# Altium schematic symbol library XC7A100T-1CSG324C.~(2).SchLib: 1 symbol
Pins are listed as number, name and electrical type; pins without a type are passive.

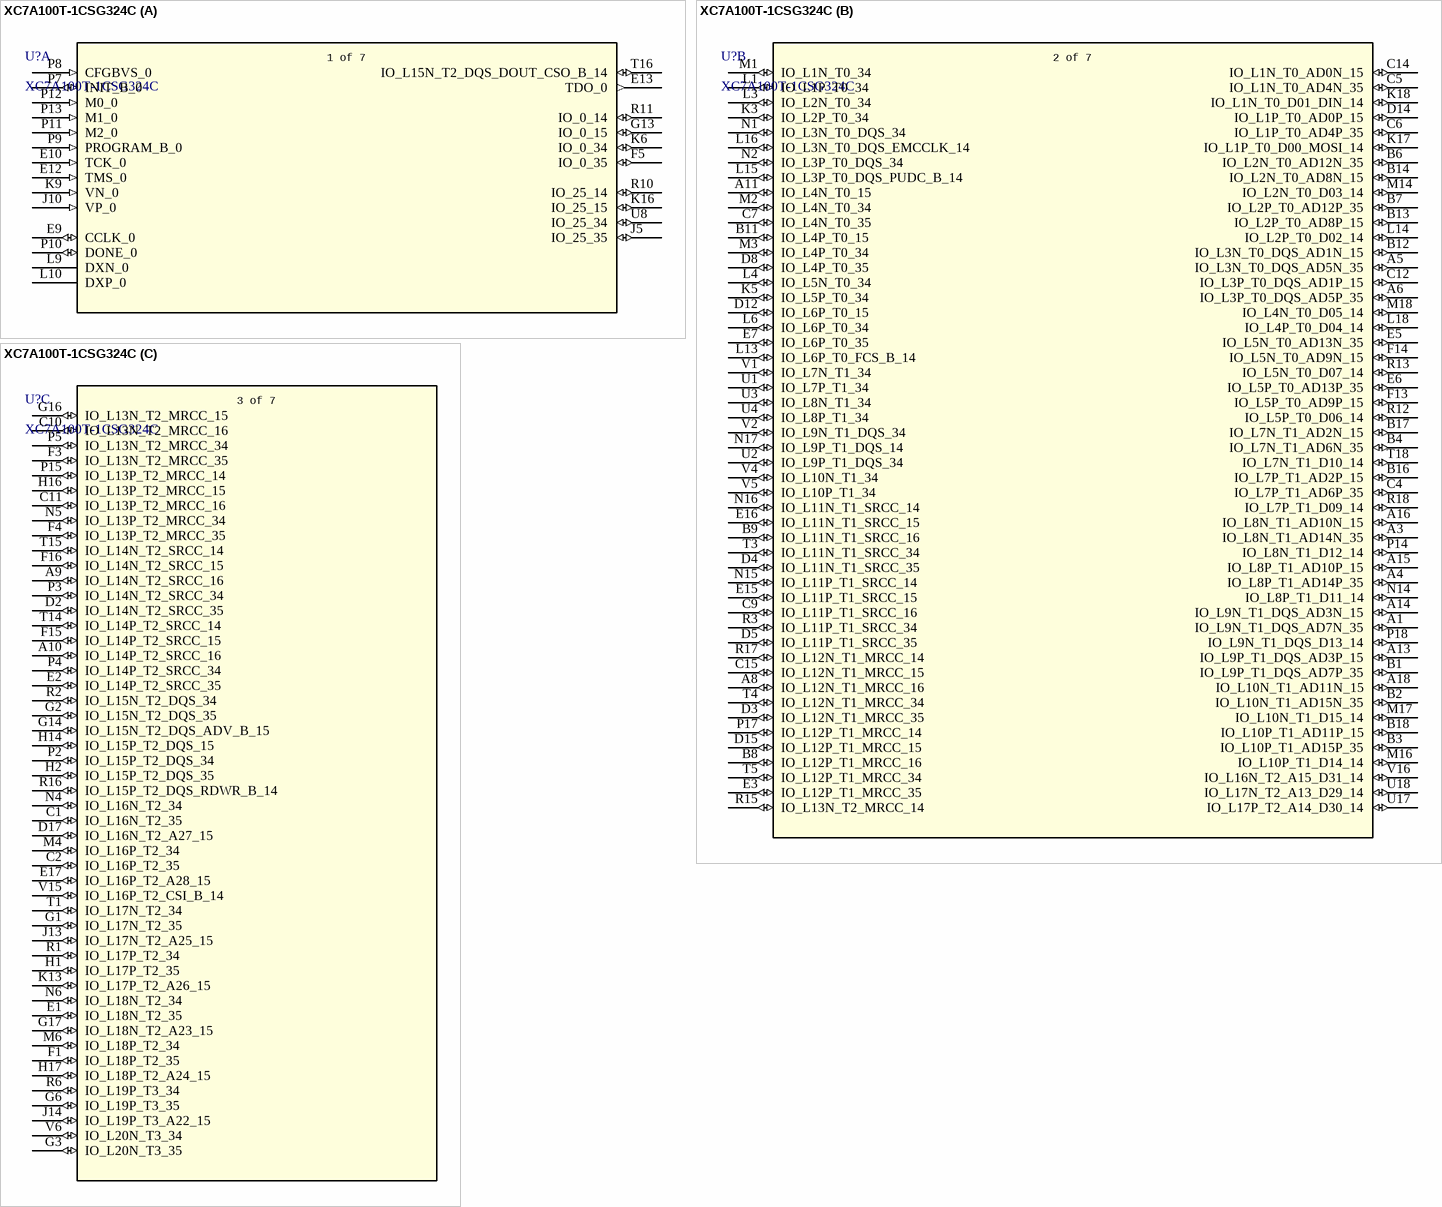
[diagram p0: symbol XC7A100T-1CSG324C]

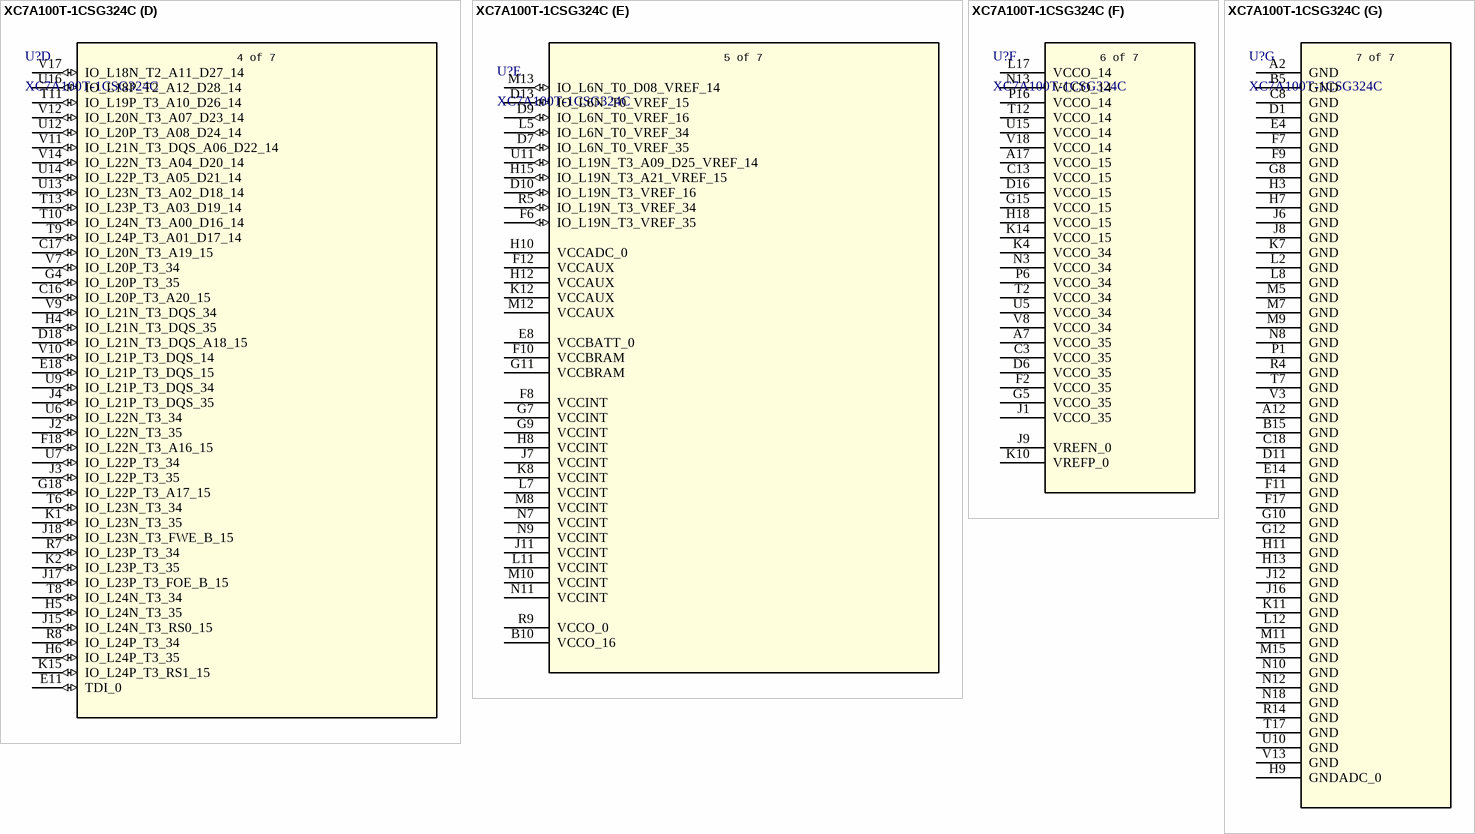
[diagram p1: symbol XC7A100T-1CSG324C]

## XC7A100T-1CSG324C
designator U?
Description; Manufacturer_Name: Xilinx Inc
footprint CSG324_XIL
part A pins: E9 CCLK_0 (io), E10 TCK_0 (in), E12 TMS_0 (in), E13 TDO_0 (out), F5 IO_0_35 (io), G13 IO_0_15 (io), J5 IO_25_35 (io), J10 VP_0 (in), K6 IO_0_34 (io), K9 VN_0 (in), K16 IO_25_15 (io), L9 DXN_0, L10 DXP_0, P7 INIT_B_0 (io), P8 CFGBVS_0 (in), P9 PROGRAM_B_0 (in), P10 DONE_0 (io), P11 M2_0 (in), P12 M0_0 (in), P13 M1_0 (in), R10 IO_25_14 (io), R11 IO_0_14 (io), T16 IO_L15N_T2_DQS_DOUT_CSO_B_14 (io), U8 IO_25_34 (io)
part B pins: A1 IO_L9N_T1_DQS_AD7N_35 (io), A3 IO_L8N_T1_AD14N_35 (io), A4 IO_L8P_T1_AD14P_35 (io), A5 IO_L3N_T0_DQS_AD5N_35 (io), A6 IO_L3P_T0_DQS_AD5P_35 (io), A8 IO_L12N_T1_MRCC_16 (io), A11 IO_L4N_T0_15 (io), A13 IO_L9P_T1_DQS_AD3P_15 (io), A14 IO_L9N_T1_DQS_AD3N_15 (io), A15 IO_L8P_T1_AD10P_15 (io), A16 IO_L8N_T1_AD10N_15 (io), A18 IO_L10N_T1_AD11N_15 (io), B1 IO_L9P_T1_DQS_AD7P_35 (io), B2 IO_L10N_T1_AD15N_35 (io), B3 IO_L10P_T1_AD15P_35 (io), B4 IO_L7N_T1_AD6N_35 (io), B6 IO_L2N_T0_AD12N_35 (io), B7 IO_L2P_T0_AD12P_35 (io), B8 IO_L12P_T1_MRCC_16 (io), B9 IO_L11N_T1_SRCC_16 (io), B11 IO_L4P_T0_15 (io), B12 IO_L3N_T0_DQS_AD1N_15 (io), B13 IO_L2P_T0_AD8P_15 (io), B14 IO_L2N_T0_AD8N_15 (io), B16 IO_L7P_T1_AD2P_15 (io), B17 IO_L7N_T1_AD2N_15 (io), B18 IO_L10P_T1_AD11P_15 (io), C4 IO_L7P_T1_AD6P_35 (io), C5 IO_L1N_T0_AD4N_35 (io), C6 IO_L1P_T0_AD4P_35 (io), C7 IO_L4N_T0_35 (io), C9 IO_L11P_T1_SRCC_16 (io), C12 IO_L3P_T0_DQS_AD1P_15 (io), C14 IO_L1N_T0_AD0N_15 (io), C15 IO_L12N_T1_MRCC_15 (io), D3 IO_L12N_T1_MRCC_35 (io), D4 IO_L11N_T1_SRCC_35 (io), D5 IO_L11P_T1_SRCC_35 (io), D8 IO_L4P_T0_35 (io), D12 IO_L6P_T0_15 (io), D14 IO_L1P_T0_AD0P_15 (io), D15 IO_L12P_T1_MRCC_15 (io), E3 IO_L12P_T1_MRCC_35 (io), E5 IO_L5N_T0_AD13N_35 (io), E6 IO_L5P_T0_AD13P_35 (io), E7 IO_L6P_T0_35 (io), E15 IO_L11P_T1_SRCC_15 (io), E16 IO_L11N_T1_SRCC_15 (io), F13 IO_L5P_T0_AD9P_15 (io), F14 IO_L5N_T0_AD9N_15 (io), K3 IO_L2P_T0_34 (io), K5 IO_L5P_T0_34 (io), K17 IO_L1P_T0_D00_MOSI_14 (io), K18 IO_L1N_T0_D01_DIN_14 (io), L1 IO_L1P_T0_34 (io), L3 IO_L2N_T0_34 (io), L4 IO_L5N_T0_34 (io), L6 IO_L6P_T0_34 (io), L13 IO_L6P_T0_FCS_B_14 (io), L14 IO_L2P_T0_D02_14 (io), L15 IO_L3P_T0_DQS_PUDC_B_14 (io), L16 IO_L3N_T0_DQS_EMCCLK_14 (io), L18 IO_L4P_T0_D04_14 (io), M1 IO_L1N_T0_34 (io), M2 IO_L4N_T0_34 (io), M3 IO_L4P_T0_34 (io), M14 IO_L2N_T0_D03_14 (io), M16 IO_L10P_T1_D14_14 (io), M17 IO_L10N_T1_D15_14 (io), M18 IO_L4N_T0_D05_14 (io), N1 IO_L3N_T0_DQS_34 (io), N2 IO_L3P_T0_DQS_34 (io), N14 IO_L8P_T1_D11_14 (io), N15 IO_L11P_T1_SRCC_14 (io), N16 IO_L11N_T1_SRCC_14 (io), N17 IO_L9P_T1_DQS_14 (io), P14 IO_L8N_T1_D12_14 (io), P17 IO_L12P_T1_MRCC_14 (io), P18 IO_L9N_T1_DQS_D13_14 (io), R3 IO_L11P_T1_SRCC_34 (io), R12 IO_L5P_T0_D06_14 (io), R13 IO_L5N_T0_D07_14 (io), R15 IO_L13N_T2_MRCC_14 (io), R17 IO_L12N_T1_MRCC_14 (io), R18 IO_L7P_T1_D09_14 (io), T3 IO_L11N_T1_SRCC_34 (io), T4 IO_L12N_T1_MRCC_34 (io), T5 IO_L12P_T1_MRCC_34 (io), T18 IO_L7N_T1_D10_14 (io), U1 IO_L7P_T1_34 (io), U2 IO_L9P_T1_DQS_34 (io), U3 IO_L8N_T1_34 (io), U4 IO_L8P_T1_34 (io), U17 IO_L17P_T2_A14_D30_14 (io), U18 IO_L17N_T2_A13_D29_14 (io), V1 IO_L7N_T1_34 (io), V2 IO_L9N_T1_DQS_34 (io), V4 IO_L10N_T1_34 (io), V5 IO_L10P_T1_34 (io), V16 IO_L16N_T2_A15_D31_14 (io)
part C pins: A9 IO_L14N_T2_SRCC_16 (io), A10 IO_L14P_T2_SRCC_16 (io), C1 IO_L16N_T2_35 (io), C2 IO_L16P_T2_35 (io), C10 IO_L13N_T2_MRCC_16 (io), C11 IO_L13P_T2_MRCC_16 (io), D2 IO_L14N_T2_SRCC_35 (io), D17 IO_L16N_T2_A27_15 (io), E1 IO_L18N_T2_35 (io), E2 IO_L14P_T2_SRCC_35 (io), E17 IO_L16P_T2_A28_15 (io), F1 IO_L18P_T2_35 (io), F3 IO_L13N_T2_MRCC_35 (io), F4 IO_L13P_T2_MRCC_35 (io), F15 IO_L14P_T2_SRCC_15 (io), F16 IO_L14N_T2_SRCC_15 (io), G1 IO_L17N_T2_35 (io), G2 IO_L15N_T2_DQS_35 (io), G3 IO_L20N_T3_35 (io), G6 IO_L19P_T3_35 (io), G14 IO_L15N_T2_DQS_ADV_B_15 (io), G16 IO_L13N_T2_MRCC_15 (io), G17 IO_L18N_T2_A23_15 (io), H1 IO_L17P_T2_35 (io), H2 IO_L15P_T2_DQS_35 (io), H14 IO_L15P_T2_DQS_15 (io), H16 IO_L13P_T2_MRCC_15 (io), H17 IO_L18P_T2_A24_15 (io), J13 IO_L17N_T2_A25_15 (io), J14 IO_L19P_T3_A22_15 (io), K13 IO_L17P_T2_A26_15 (io), M4 IO_L16P_T2_34 (io), M6 IO_L18P_T2_34 (io), N4 IO_L16N_T2_34 (io), N5 IO_L13P_T2_MRCC_34 (io), N6 IO_L18N_T2_34 (io), P2 IO_L15P_T2_DQS_34 (io), P3 IO_L14N_T2_SRCC_34 (io), P4 IO_L14P_T2_SRCC_34 (io), P5 IO_L13N_T2_MRCC_34 (io), P15 IO_L13P_T2_MRCC_14 (io), R1 IO_L17P_T2_34 (io), R2 IO_L15N_T2_DQS_34 (io), R6 IO_L19P_T3_34 (io), R16 IO_L15P_T2_DQS_RDWR_B_14 (io), T1 IO_L17N_T2_34 (io), T14 IO_L14P_T2_SRCC_14 (io), T15 IO_L14N_T2_SRCC_14 (io), V6 IO_L20N_T3_34 (io), V15 IO_L16P_T2_CSI_B_14 (io)
part D pins: C16 IO_L20P_T3_A20_15 (io), C17 IO_L20N_T3_A19_15 (io), D18 IO_L21N_T3_DQS_A18_15 (io), E11 TDI_0 (io), E18 IO_L21P_T3_DQS_15 (io), F18 IO_L22N_T3_A16_15 (io), G4 IO_L20P_T3_35 (io), G18 IO_L22P_T3_A17_15 (io), H4 IO_L21N_T3_DQS_35 (io), H5 IO_L24N_T3_35 (io), H6 IO_L24P_T3_35 (io), J2 IO_L22N_T3_35 (io), J3 IO_L22P_T3_35 (io), J4 IO_L21P_T3_DQS_35 (io), J15 IO_L24N_T3_RS0_15 (io), J17 IO_L23P_T3_FOE_B_15 (io), J18 IO_L23N_T3_FWE_B_15 (io), K1 IO_L23N_T3_35 (io), K2 IO_L23P_T3_35 (io), K15 IO_L24P_T3_RS1_15 (io), R7 IO_L23P_T3_34 (io), R8 IO_L24P_T3_34 (io), T6 IO_L23N_T3_34 (io), T8 IO_L24N_T3_34 (io), T9 IO_L24P_T3_A01_D17_14 (io), T10 IO_L24N_T3_A00_D16_14 (io), T11 IO_L19P_T3_A10_D26_14 (io), T13 IO_L23P_T3_A03_D19_14 (io), U6 IO_L22N_T3_34 (io), U7 IO_L22P_T3_34 (io), U9 IO_L21P_T3_DQS_34 (io), U12 IO_L20P_T3_A08_D24_14 (io), U13 IO_L23N_T3_A02_D18_14 (io), U14 IO_L22P_T3_A05_D21_14 (io), U16 IO_L18P_T2_A12_D28_14 (io), V7 IO_L20P_T3_34 (io), V9 IO_L21N_T3_DQS_34 (io), V10 IO_L21P_T3_DQS_14 (io), V11 IO_L21N_T3_DQS_A06_D22_14 (io), V12 IO_L20N_T3_A07_D23_14 (io), V14 IO_L22N_T3_A04_D20_14 (io), V17 IO_L18N_T2_A11_D27_14 (io)
part E pins: B10 VCCO_16 (power), D7 IO_L6N_T0_VREF_35 (io), D9 IO_L6N_T0_VREF_16 (io), D10 IO_L19N_T3_VREF_16 (io), D13 IO_L6N_T0_VREF_15 (io), E8 VCCBATT_0 (power), F6 IO_L19N_T3_VREF_35 (io), F8 VCCINT (power), F10 VCCBRAM (power), F12 VCCAUX (power), G7 VCCINT (power), G9 VCCINT (power), G11 VCCBRAM (power), H8 VCCINT (power), H10 VCCADC_0 (power), H12 VCCAUX (power), H15 IO_L19N_T3_A21_VREF_15 (io), J7 VCCINT (power), J11 VCCINT (power), K8 VCCINT (power), K12 VCCAUX (power), L5 IO_L6N_T0_VREF_34 (io), L7 VCCINT (power), L11 VCCINT (power), M8 VCCINT (power), M10 VCCINT (power), M12 VCCAUX (power), M13 IO_L6N_T0_D08_VREF_14 (io), N7 VCCINT (power), N9 VCCINT (power), N11 VCCINT (power), R5 IO_L19N_T3_VREF_34 (io), R9 VCCO_0 (power), U11 IO_L19N_T3_A09_D25_VREF_14 (io)
part F pins: A7 VCCO_35 (power), A17 VCCO_15 (power), C3 VCCO_35 (power), C13 VCCO_15 (power), D6 VCCO_35 (power), D16 VCCO_15 (power), F2 VCCO_35 (power), G5 VCCO_35 (power), G15 VCCO_15 (power), H18 VCCO_15 (power), J1 VCCO_35 (power), J9 VREFN_0 (power), K4 VCCO_34 (power), K10 VREFP_0 (power), K14 VCCO_15 (power), L17 VCCO_14 (power), N3 VCCO_34 (power), N13 VCCO_14 (power), P6 VCCO_34 (power), P16 VCCO_14 (power), T2 VCCO_34 (power), T12 VCCO_14 (power), U5 VCCO_34 (power), U15 VCCO_14 (power), V8 VCCO_34 (power), V18 VCCO_14 (power)
part G pins: A2 GND (power), A12 GND (power), B5 GND (power), B15 GND (power), C8 GND (power), C18 GND (power), D1 GND (power), D11 GND (power), E4 GND (power), E14 GND (power), F7 GND (power), F9 GND (power), F11 GND (power), F17 GND (power), G8 GND (power), G10 GND (power), G12 GND (power), H3 GND (power), H7 GND (power), H9 GNDADC_0 (power), H11 GND (power), H13 GND (power), J6 GND (power), J8 GND (power), J12 GND (power), J16 GND (power), K7 GND (power), K11 GND (power), L2 GND (power), L8 GND (power), L12 GND (power), M5 GND (power), M7 GND (power), M9 GND (power), M11 GND (power), M15 GND (power), N8 GND (power), N10 GND (power), N12 GND (power), N18 GND (power), P1 GND (power), R4 GND (power), R14 GND (power), T7 GND (power), T17 GND (power), U10 GND (power), V3 GND (power), V13 GND (power)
